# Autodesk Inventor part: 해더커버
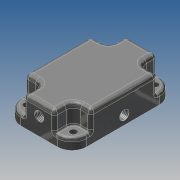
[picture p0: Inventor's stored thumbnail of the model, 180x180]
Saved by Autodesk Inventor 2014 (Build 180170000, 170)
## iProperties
Company: 한국ATC센터
Created: 2014-01
Part Number: 해더커버
Document SubType Name: Modeling
Designer: KYOUNG IL JANG
Density: 1 g/cm^3
Material: 알루미늄 6061
Mass: 45.8304 g
Surface Area: 122.39 cm^2
Volume: 45.8304 cm^3
Vendor: CBT Solutions
Appearance: 매끄러움 - 중간 회색
Author: KYOUNG IL JANG
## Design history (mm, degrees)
sketch "스케치1"
  geometry: L1 (22.5, -32)-(22.5, 25) reference; L2 (-19.5, -35)-(19.5, -35) reference; L3 (-22.5, 25)-(-22.5, -32) reference; L4 (12.5, 35)-(-12.5, 35) reference; A1 r 10 centre (12.5, 25) between (22.5, 25) and (12.5, 35) reference; A2 r 3 centre (19.5, -32) between (19.5, -35) and (22.5, -32) reference; A3 r 3 centre (-19.5, -32) between (-22.5, -32) and (-19.5, -35) reference; A4 r 10 centre (-12.5, 25) between (-12.5, 35) and (-22.5, 25) reference; 1 further point
extrude "돌출1" new body sketch "스케치1" distance "d0" = 20; taper "d1" = 0 deg
extrude "돌출2" cut sketch "스케치2" distance "d5" = 13; taper "d6" = 0 deg
fillet "모깎기1" dims "d7" = 5
fillet "모깎기2" dims "d8" = 1
fillet "모깎기3" dims "d9" = 2
fillet "모깎기4" dims "d10" = 3
sketch "스케치3"
  geometry: L1 (-21.5, -1)-(-8.5, -1) reference; L2 (10.5, -1)-(23.5, -1) reference; L3 (-32, 0)-(25, 0) reference; L4 (-15, -1)-(-15, 0); L5 (17, -1)-(17, 0); L6 (-2.75, 0)-(-2.75, 7); L7 (-15, 7)-(-2.75, 7); L8 (-15, 0)-(-15, 7); L9 (17, 0)-(17, 7); L10 (4.75, 0)-(4.75, 7); L11 (4.75, 7)-(17, 7); 1 further point
  constraints: 16 end point, 7 parallel, 4 perpendicular, 4 point on line, 2 midpoint, 1 horizontal alignment
  dimensions: "d11" = 8 distance of L5.start L9.end; "d12" = 24.5 diameter of L6 L8; "d13" = 24.5 diameter of L10 L9 (= d12)
  node "참조15"
  node "참조16"
  node "참조17"
revolve "회전1" stored, may be unused: angle "d14" = 90 deg
revolve "회전2" stored, may be unused: angle "d15" = 90 deg
fillet "모깎기5" dims "d16" = 5
sketch "스케치4"
  geometry: C1 r 2.229 at (16, -27.5) reference; C2 r 2.229 at (16, 28.5) reference; C3 r 2.229 at (-16, -27.5) reference; C4 r 2.229 at (-16, 28.5) reference; 1 further point
hole "구멍1" sketch "스케치4" at (16, -27.5), (-16, -27.5), (16, 28.5), (-16, 28.5) diameter "d17" = 4.5; stored, may be unused: countersink angle "d21" = 90 deg, drill point angle "d23" = 118 deg; dims "d18" = 6, "d19" = 4, "d20" = 2, "d22" = 8
sketch "스케치5"
  geometry: L1 (-20.09, 3.496)-(-22.691, 8); L2 (-29.619, 12)-(-37.219, 12); L3 (-35, 0)-(-32, 0) reference; L4 (-35, 8)-(-35, 17) reference; L5 (36.506, 12)-(30.619, 12); L6 (23.691, 8)-(20.656, 2.744); L7 (35, 17)-(35, 8) reference; A1 r 8 centre (-29.619, 4) between (-22.691, 8) and (-29.619, 12); A2 r 8 centre (30.619, 4) between (30.619, 12) and (23.691, 8); 5 further points
  constraints: 8 end point, 8 point on line, 4 point on circle, 4 tangent, 2 centre point, 1 collinear, 1 horizontal, 1 perpendicular
  dimensions: "d24" = 12 distance between parallel lines of L2 L3; "d25" = 10 distance from line of point (-25, 12) L4; "d26" = 120 deg angle of L1 L2; "d27" = 8 radius of A1; "d29" = 9 distance from line of point (26, 12) L7; "d30" = 120 deg angle of L6 L5; "d31" = 8 radius of A2
node "작업점1"
node "작업점2"
hole "구멍2" diameter "d34" = 5.944; stored, may be unused: countersink angle "d40" = 90 deg, drill point angle "d42" = 0 deg; dims "d32" = 10, "d33" = 10, "d35" = 6.886, "d36" = 0.62479, "d37" = 5.959, "d38" = 4, "d39" = 2, "d41" = 6.9
hole "구멍3" diameter "d45" = 5.944; stored, may be unused: countersink angle "d51" = 90 deg, drill point angle "d53" = 0 deg; dims "d43" = 10, "d44" = 10, "d46" = 6.886, "d47" = 0.62479, "d48" = 5.959, "d49" = 4, "d50" = 2, "d52" = 6.9
sketch "스케치6"
  geometry: C1 r 2.972 at (19.5, 12) reference; 1 further point
feature "스윕1" sketch "스케치6" dims "d54" = 0
sketch "스케치7"
  geometry: C1 r 2.972 at (12.5, -12) reference; 1 further point
feature "스윕2" sketch "스케치7" dims "d55" = 0
sketch "스케치8"
  geometry: L1 (0, 36.75)-(0, 61.25) reference; L2 (0, 4.75)-(0, 29.25) reference; L3 (0, 36.75)-(0, 29.25); 3 further points
  constraints: 2 end point, 1 collinear, 1 horizontal alignment, 1 midpoint
  dimensions: "d57" = 6 distance of point (6, 33) point (0, 33)
hole "구멍4" sketch "스케치8" at (6, 33) diameter "d58" = 5.944; stored, may be unused: countersink angle "d64" = 90 deg, drill point angle "d66" = 0 deg; dims "d59" = 6.886, "d60" = 0.62479, "d61" = 5.959, "d62" = 4, "d63" = 2, "d65" = 6.9
sketch "스케치10"
  geometry: C1 r 2.972 at (0, 0) reference; 1 further point
  node "투영된 루프4"
sketch "스케치11"
  geometry: C1 r 2.972 at (0, 0) reference; 1 further point
  node "투영된 루프5"
node "작업축3"
node "작업 평면2"
sketch "스케치12"
  geometry: L1 (3.443, -2.979)-(3.443, 2.98) reference; L2 (3.443, 0)-(11.057, 0); L3 (19.057, -8)-(19.057, -11.414); A1 r 8 centre (11.057, -8) between (19.057, -8) and (11.057, 0); 2 further points
  constraints: 4 end point, 2 perpendicular, 2 point on circle, 2 point on line, 2 tangent, 1 centre point, 1 midpoint, 1 vertical alignment
  dimensions: "d70" = 8 radius of A1
feature "스윕3" sketch "스케치12" dims "d71" = 0
node "작업 평면3"
sketch "스케치13"
  geometry: L1 (34.657, -2.972)-(34.657, 2.972) reference; L2 (34.657, 0)-(27.057, 0); L3 (19.057, 8)-(19.057, 10.673); A1 r 8 centre (27.057, 8) between (19.057, 8) and (27.057, 0); 1 further point
  constraints: 4 end point, 2 perpendicular, 2 point on circle, 2 tangent, 1 centre point, 1 midpoint, 1 point on line
  dimensions: "d73" = 8 radius of A1
feature "스윕4" sketch "스케치13" dims "d74" = 0
feature "면 삭제1"
fillet "모깎기6" dims "d75" = 10
node "솔리드1"
mirror "대칭1"
node "참조1"
node "참조2"
node "참조3"
node "참조4"
node "참조5"
node "참조6"
node "참조7"
node "참조8"
node "참조18"
node "참조19"
node "참조20"
node "참조21"
node "투영된 루프2"
node "투영된 루프3"
other parameters: "d2" = 12, "d3" = 5.5 (derived), "d4" = 5.5, "d69" = -15 deg, "d72" = 15 deg
